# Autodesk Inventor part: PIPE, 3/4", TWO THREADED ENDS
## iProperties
Title: PIPE, 3/4", TWO THREADED ENDS
Author: Administrator
Shininess: 60.0
PropertySet Name: _Private Model Information
Created: 2001-04
Part Number: 3/4" PIPE
Material: Steel, Mild
Document SubType Name: Modeling
Designer: Administrator
Control State: 0
Master: False
Checked Out: False
PropertySet Name: Design Tracking Control
Density: 7.86
Volumn: 14.15699511414508
Area: 164.85894032490236
PropertySet Name: Model Information
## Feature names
1. Extrusion1
2. Revolution1
3. Mirror1
